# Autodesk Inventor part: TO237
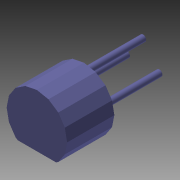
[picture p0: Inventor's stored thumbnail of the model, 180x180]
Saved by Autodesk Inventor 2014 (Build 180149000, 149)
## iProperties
Shininess: 64.0
Length Units: 11272
Angle Units: 11279
Time Units: 11290
Mass Units: 11286
Length Display Precision: 3
Angle Display Precision: 2
Compacted: True
Part Number: TO237
Document SubType Name: Modeling
Created: 2003-04
Designer: t_enrig
Manufacturer: Standard
Standards Organization: Custom
Density: 1 g/cm^3
Mass: 0.0822443 g
Surface Area: 1.29159 cm^2
Volume: 0.0822443 cm^3
Material: Generic
Appearance: TranslatedColorStyle
Density: 0.0
Volumn: 0.0
Area: 0.0
PropertySet Name: Model Information
Control State: 0
Master: False
Checked Out: False
Author: t_enrig
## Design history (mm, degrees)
feature "Base1"
body "Solid1"
